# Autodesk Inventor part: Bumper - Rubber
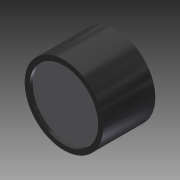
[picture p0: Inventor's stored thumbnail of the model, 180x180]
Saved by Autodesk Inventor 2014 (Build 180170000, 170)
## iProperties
Company: NHTSA/VRTC
Created: 2012-08
Material: Rubber
Document SubType Name: Modeling
Designer: Mike Vanvoorhis
Density: 0.93 g/cm^3
Mass: 27.1258 g
Surface Area: 53.5336 cm^2
Volume: 29.1675 cm^3
Project: CHILD SIDE IMPACT SLED
Description: BUMPER - RUBBER
Appearance: Rubber - Black - Version 1.1
Author: Dave Walker
Title: Bumper - Rubber
Subject: Child side Impact Sled
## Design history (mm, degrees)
sketch "Sketch1"
  geometry: C1 r 19.05 at (0, 0); 1 further point
  constraints: 1 centre point, 1 coincident
  dimensions: "d0" = 38.1 diameter of C1
extrude "Extrusion1" new body sketch "Sketch1" distance "d1" = 25.4; taper "d2" = 0 deg
sketch "Sketch4"
  geometry: C1 r 19.05 at (0, 0) reference; C2 r 16.669 at (0, 0)
  constraints: 1 centre point, 1 coincident
  dimensions: "d24" = 33.3375 diameter of C2
extrude "Extrusion4" cut sketch "Sketch4" distance "d25" = 1.524; taper "d26" = 0 deg
body "Solid1"
